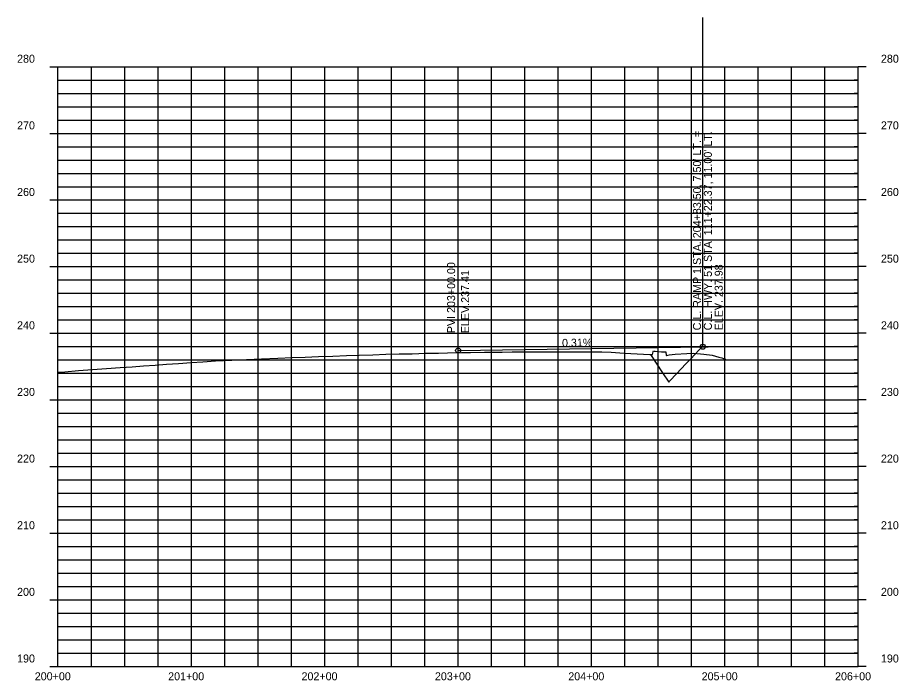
# Model space of a CAD drawing. Extents: x 921603 to 924670, y 1759276 to 1766491.
# Drawn here: x 921610 to 922270, y 1763922 to 1764419 of the extents above; entities that cross this region are included whole.
import ezdxf

# ---------------------------------------------------------------- set-up
doc = ezdxf.new("R2010")
doc.units = 0
for name, color, linetype in [('63', 7, 'Continuous'), ('R_Axis_Annotation', 7, 'Continuous'), ('R_Exist Surface', 7, 'Continuous'), ('R_Grid', 7, 'Continuous'), ('R_Grid Annot', 7, 'Continuous'), ('R_Grid_Minor', 7, 'Continuous'), ('R_Prop Surface', 7, 'Continuous'), ('R_Vert Alg', 7, 'Continuous'), ('R_Vert Alg Annot', 7, 'Continuous')]:
    doc.layers.add(name, color=color, linetype=linetype)

msp = doc.modelspace()

# ---------------------------------------------------------------- linework, layer by layer
at = {"layer": 'R_Exist Surface'}
msp.add_lwpolyline([(921639.83, 1764153.1), (921644.89, 1764153.44), (921655.24, 1764154.22), (921665.73, 1764155.01), (921676.14, 1764155.79), (921686.57, 1764156.57), (921695.41, 1764157.21), (921703.94, 1764157.79), (921712.75, 1764158.42), (921721.3, 1764159), (921730.18, 1764159.68), (921739.57, 1764160.24), (921748.44, 1764160.92), (921757.85, 1764161.49), (921770.14, 1764162.03), (921781.25, 1764162.57), (921792.41, 1764163.11), (921804.66, 1764163.65), (921815.33, 1764164.06), (921825.24, 1764164.4), (921835.2, 1764164.74), (921845.82, 1764165.15), (921856.12, 1764165.51), (921865.74, 1764165.82), (921875.99, 1764166.17), (921885.66, 1764166.48), (921895.52, 1764166.77), (921905.37, 1764166.96), (921915.3, 1764167.25), (921925.09, 1764167.43), (921931.78, 1764167.48), (921942.35, 1764167.75), (921949.03, 1764167.79), (921959.64, 1764168.07), (921966.31, 1764168.11), (921972.96, 1764168.15), (921980.28, 1764168.28), (921992.27, 1764168.27), (921999.25, 1764168.38), (921999.45, 1764168.39), (922004.63, 1764168.38), (922020.25, 1764168.36), (922027.49, 1764168.32), (922028.2, 1764168.36), (922029.24, 1764168.44), (922036.73, 1764168.34), (922041.05, 1764168.32), (922047.65, 1764168.23), (922054.47, 1764167.97), (922064.29, 1764167.35), (922069.42, 1764167.21), (922083.53, 1764166.28), (922084.11, 1764166.26), (922085.62, 1764166.29), (922086.09, 1764168.32), (922086.29, 1764168.99), (922086.8, 1764168.83), (922087.46, 1764168.76), (922089.9, 1764168.61), (922092.39, 1764168.39), (922093.96, 1764168.4), (922095.17, 1764168.29), (922095.19, 1764168.28), (922095.59, 1764168.26), (922095.64, 1764168.25), (922095.65, 1764168.23), (922095.88, 1764165.5), (922095.94, 1764165.48), (922097.07, 1764165.93), (922098.01, 1764166.06), (922102.53, 1764166.7), (922111.27, 1764167.11), (922116.36, 1764167.36), (922124.05, 1764166.49), (922130.33, 1764165.73), (922135.25, 1764164.39), (922137.44, 1764163.82), (922138.89, 1764163.33), (922139.87, 1764163.04), (922140.24, 1764162.82)], dxfattribs=at)
at = {"layer": 'R_Grid'}
for p, q in [((921639.83, 1763932.26), (921639.83, 1764382.26)), ((921639.83, 1764382.26), (922239.83, 1764382.26)), ((921639.83, 1764382.26), (922239.83, 1764382.26)), ((921739.83, 1763932.26), (921739.83, 1764382.26)), ((921839.83, 1763932.26), (921839.83, 1764382.26)), ((921939.83, 1763932.26), (921939.83, 1764382.26)), ((922039.83, 1763932.26), (922039.83, 1764382.26)), ((922139.83, 1763932.26), (922139.83, 1764382.26)), ((922239.83, 1763932.26), (922239.83, 1764382.26)), ((921639.83, 1764332.26), (922239.83, 1764332.26)), ((921639.83, 1764282.26), (922239.83, 1764282.26)), ((921639.83, 1764232.26), (922239.83, 1764232.26)), ((921639.83, 1764182.26), (922239.83, 1764182.26)), ((921639.83, 1764132.26), (922239.83, 1764132.26)), ((921639.83, 1764082.26), (922239.83, 1764082.26)), ((921639.83, 1764032.26), (922239.83, 1764032.26)), ((921639.83, 1763982.26), (922239.83, 1763982.26)), ((921639.83, 1763932.26), (922239.83, 1763932.26))]:
    msp.add_line(p, q, dxfattribs=at)
at = {"layer": 'R_Grid Annot'}
for p, q in [((921633.83, 1764382.26), (921639.83, 1764382.26)), ((921633.83, 1764382.26), (921639.83, 1764382.26)), ((922245.83, 1764382.26), (922239.83, 1764382.26)), ((922245.83, 1764382.26), (922239.83, 1764382.26)), ((921639.83, 1764372.26), (921642.83, 1764372.26)), ((922239.83, 1764372.26), (922236.83, 1764372.26)), ((921639.83, 1764362.26), (921642.83, 1764362.26)), ((922239.83, 1764362.26), (922236.83, 1764362.26)), ((921639.83, 1764352.26), (921642.83, 1764352.26)), ((922239.83, 1764352.26), (922236.83, 1764352.26)), ((921639.83, 1764342.26), (921642.83, 1764342.26)), ((922239.83, 1764342.26), (922236.83, 1764342.26)), ((921633.83, 1764332.26), (921639.83, 1764332.26)), ((922245.83, 1764332.26), (922239.83, 1764332.26)), ((921639.83, 1764322.26), (921642.83, 1764322.26)), ((922239.83, 1764322.26), (922236.83, 1764322.26)), ((921639.83, 1764312.26), (921642.83, 1764312.26)), ((922239.83, 1764312.26), (922236.83, 1764312.26)), ((921639.83, 1764302.26), (921642.83, 1764302.26)), ((922239.83, 1764302.26), (922236.83, 1764302.26)), ((921639.83, 1764292.26), (921642.83, 1764292.26)), ((922239.83, 1764292.26), (922236.83, 1764292.26)), ((921633.83, 1764282.26), (921639.83, 1764282.26)), ((922245.83, 1764282.26), (922239.83, 1764282.26)), ((921639.83, 1764272.26), (921642.83, 1764272.26)), ((922239.83, 1764272.26), (922236.83, 1764272.26)), ((921639.83, 1764262.26), (921642.83, 1764262.26)), ((922239.83, 1764262.26), (922236.83, 1764262.26)), ((921639.83, 1764252.26), (921642.83, 1764252.26)), ((922239.83, 1764252.26), (922236.83, 1764252.26)), ((921639.83, 1764242.26), (921642.83, 1764242.26)), ((922239.83, 1764242.26), (922236.83, 1764242.26)), ((921633.83, 1764232.26), (921639.83, 1764232.26)), ((922245.83, 1764232.26), (922239.83, 1764232.26)), ((921639.83, 1764222.26), (921642.83, 1764222.26)), ((922239.83, 1764222.26), (922236.83, 1764222.26)), ((921639.83, 1764212.26), (921642.83, 1764212.26)), ((922239.83, 1764212.26), (922236.83, 1764212.26)), ((921639.83, 1764202.26), (921642.83, 1764202.26)), ((922239.83, 1764202.26), (922236.83, 1764202.26)), ((921639.83, 1764192.26), (921642.83, 1764192.26)), ((922239.83, 1764192.26), (922236.83, 1764192.26)), ((921633.83, 1764182.26), (921639.83, 1764182.26)), ((922245.83, 1764182.26), (922239.83, 1764182.26)), ((921639.83, 1764172.26), (921642.83, 1764172.26)), ((922239.83, 1764172.26), (922236.83, 1764172.26)), ((921639.83, 1764162.26), (921642.83, 1764162.26)), ((922239.83, 1764162.26), (922236.83, 1764162.26)), ((921639.83, 1764152.26), (921642.83, 1764152.26)), ((922239.83, 1764152.26), (922236.83, 1764152.26)), ((921639.83, 1764142.26), (921642.83, 1764142.26)), ((922239.83, 1764142.26), (922236.83, 1764142.26)), ((921633.83, 1764132.26), (921639.83, 1764132.26)), ((922245.83, 1764132.26), (922239.83, 1764132.26)), ((921639.83, 1764122.26), (921642.83, 1764122.26)), ((922239.83, 1764122.26), (922236.83, 1764122.26)), ((921639.83, 1764112.26), (921642.83, 1764112.26)), ((922239.83, 1764112.26), (922236.83, 1764112.26)), ((921639.83, 1764102.26), (921642.83, 1764102.26)), ((922239.83, 1764102.26), (922236.83, 1764102.26)), ((921639.83, 1764092.26), (921642.83, 1764092.26)), ((922239.83, 1764092.26), (922236.83, 1764092.26)), ((921633.83, 1764082.26), (921639.83, 1764082.26)), ((922245.83, 1764082.26), (922239.83, 1764082.26)), ((921639.83, 1764072.26), (921642.83, 1764072.26)), ((922239.83, 1764072.26), (922236.83, 1764072.26)), ((921639.83, 1764062.26), (921642.83, 1764062.26)), ((922239.83, 1764062.26), (922236.83, 1764062.26)), ((921639.83, 1764052.26), (921642.83, 1764052.26)), ((922239.83, 1764052.26), (922236.83, 1764052.26)), ((921639.83, 1764042.26), (921642.83, 1764042.26)), ((922239.83, 1764042.26), (922236.83, 1764042.26)), ((921633.83, 1764032.26), (921639.83, 1764032.26)), ((922245.83, 1764032.26), (922239.83, 1764032.26)), ((921639.83, 1764022.26), (921642.83, 1764022.26)), ((922239.83, 1764022.26), (922236.83, 1764022.26)), ((921639.83, 1764012.26), (921642.83, 1764012.26)), ((922239.83, 1764012.26), (922236.83, 1764012.26)), ((921639.83, 1764002.26), (921642.83, 1764002.26)), ((922239.83, 1764002.26), (922236.83, 1764002.26)), ((921639.83, 1763992.26), (921642.83, 1763992.26)), ((922239.83, 1763992.26), (922236.83, 1763992.26)), ((921633.83, 1763982.26), (921639.83, 1763982.26)), ((922245.83, 1763982.26), (922239.83, 1763982.26)), ((921639.83, 1763972.26), (921642.83, 1763972.26)), ((922239.83, 1763972.26), (922236.83, 1763972.26)), ((921639.83, 1763962.26), (921642.83, 1763962.26)), ((922239.83, 1763962.26), (922236.83, 1763962.26)), ((921639.83, 1763952.26), (921642.83, 1763952.26)), ((922239.83, 1763952.26), (922236.83, 1763952.26)), ((921639.83, 1763942.26), (921642.83, 1763942.26)), ((922239.83, 1763942.26), (922236.83, 1763942.26)), ((921633.83, 1763932.26), (921639.83, 1763932.26)), ((922245.83, 1763932.26), (922239.83, 1763932.26))]:
    msp.add_line(p, q, dxfattribs=at)
at = {"layer": 'R_Grid_Minor'}
for p, q in [((921664.83, 1763932.26), (921664.83, 1764382.26)), ((921689.83, 1763932.26), (921689.83, 1764382.26)), ((921714.83, 1763932.26), (921714.83, 1764382.26)), ((921764.83, 1763932.26), (921764.83, 1764382.26)), ((921789.83, 1763932.26), (921789.83, 1764382.26)), ((921814.83, 1763932.26), (921814.83, 1764382.26)), ((921864.83, 1763932.26), (921864.83, 1764382.26)), ((921889.83, 1763932.26), (921889.83, 1764382.26)), ((921914.83, 1763932.26), (921914.83, 1764382.26)), ((921964.83, 1763932.26), (921964.83, 1764382.26)), ((921989.83, 1763932.26), (921989.83, 1764382.26)), ((922014.83, 1763932.26), (922014.83, 1764382.26)), ((922064.83, 1763932.26), (922064.83, 1764382.26)), ((922089.83, 1763932.26), (922089.83, 1764382.26)), ((922114.83, 1763932.26), (922114.83, 1764382.26)), ((922164.83, 1763932.26), (922164.83, 1764382.26)), ((922189.83, 1763932.26), (922189.83, 1764382.26)), ((922214.83, 1763932.26), (922214.83, 1764382.26)), ((921639.83, 1764372.26), (922239.83, 1764372.26)), ((921639.83, 1764362.26), (922239.83, 1764362.26)), ((921639.83, 1764352.26), (922239.83, 1764352.26)), ((921639.83, 1764342.26), (922239.83, 1764342.26)), ((921639.83, 1764322.26), (922239.83, 1764322.26)), ((921639.83, 1764312.26), (922239.83, 1764312.26)), ((921639.83, 1764302.26), (922239.83, 1764302.26)), ((921639.83, 1764292.26), (922239.83, 1764292.26)), ((921639.83, 1764272.26), (922239.83, 1764272.26)), ((921639.83, 1764262.26), (922239.83, 1764262.26)), ((921639.83, 1764252.26), (922239.83, 1764252.26)), ((921639.83, 1764242.26), (922239.83, 1764242.26)), ((921639.83, 1764222.26), (922239.83, 1764222.26)), ((921639.83, 1764212.26), (922239.83, 1764212.26)), ((921639.83, 1764202.26), (922239.83, 1764202.26)), ((921639.83, 1764192.26), (922239.83, 1764192.26)), ((921639.83, 1764172.26), (922239.83, 1764172.26)), ((921639.83, 1764162.26), (922239.83, 1764162.26)), ((921639.83, 1764152.26), (922239.83, 1764152.26)), ((921639.83, 1764142.26), (922239.83, 1764142.26)), ((921639.83, 1764122.26), (922239.83, 1764122.26)), ((921639.83, 1764112.26), (922239.83, 1764112.26)), ((921639.83, 1764102.26), (922239.83, 1764102.26)), ((921639.83, 1764092.26), (922239.83, 1764092.26)), ((921639.83, 1764072.26), (922239.83, 1764072.26)), ((921639.83, 1764062.26), (922239.83, 1764062.26)), ((921639.83, 1764052.26), (922239.83, 1764052.26)), ((921639.83, 1764042.26), (922239.83, 1764042.26)), ((921639.83, 1764022.26), (922239.83, 1764022.26)), ((921639.83, 1764012.26), (922239.83, 1764012.26)), ((921639.83, 1764002.26), (922239.83, 1764002.26)), ((921639.83, 1763992.26), (922239.83, 1763992.26)), ((921639.83, 1763972.26), (922239.83, 1763972.26)), ((921639.83, 1763962.26), (922239.83, 1763962.26)), ((921639.83, 1763952.26), (922239.83, 1763952.26)), ((921639.83, 1763942.26), (922239.83, 1763942.26))]:
    msp.add_line(p, q, dxfattribs=at)
at = {"layer": 'R_Prop Surface'}
msp.add_lwpolyline([(922084.18, 1764166.26), (922093.07, 1764152.71), (922097.73, 1764145.62), (922098.34, 1764146.26), (922098.57, 1764146.51), (922103.65, 1764151.9), (922110.67, 1764159.36), (922114.23, 1764163.14), (922117.22, 1764166.32), (922120.44, 1764169.74), (922122.69, 1764172.14), (922123.33, 1764172.16), (922124.81, 1764172.17), (922127.23, 1764172.2), (922135.39, 1764172.24), (922137.37, 1764172.26), (922139.71, 1764172.21)], dxfattribs=at)
at = {"layer": 'R_Vert Alg'}
msp.add_line((921939.83, 1764169.32), (922123.33, 1764172.16), dxfattribs=at)
at = {"layer": 'R_Vert Alg Annot'}
for p, q in [((922123.33, 1764182.16), (922123.33, 1764419.11)), ((921939.83, 1764179.32), (921939.83, 1764263.32)), ((921939.83, 1764169.32), (921939.83, 1764179.32)), ((922123.33, 1764172.16), (922123.33, 1764182.16))]:
    msp.add_line(p, q, dxfattribs=at)
for centre in [(922123.33, 1764172.16), (921939.83, 1764169.32)]:
    msp.add_circle(centre, 1.85, dxfattribs=at)

# ---------------------------------------------------------------- texts
at = {"layer": '63'}
msp.add_text('-', height=0.0001, dxfattribs=at).set_placement((921639.83, 1763932.26))
at = {"layer": 'R_Axis_Annotation'}
for s, p in [('280', (921609.16, 1764385.26)), ('280', (921609.16, 1764385.26)), ('280', (922256.84, 1764385.26)), ('280', (922256.84, 1764385.26)), ('270', (921609.16, 1764335.26)), ('270', (922256.84, 1764335.26)), ('260', (921609.16, 1764285.26)), ('260', (922256.84, 1764285.26)), ('250', (921609.16, 1764235.26)), ('250', (922256.84, 1764235.26)), ('240', (921609.16, 1764185.26)), ('240', (922256.84, 1764185.26)), ('230', (921609.16, 1764135.26)), ('230', (922256.84, 1764135.26)), ('220', (921609.16, 1764085.26)), ('220', (922256.84, 1764085.26)), ('210', (921609.16, 1764035.26)), ('210', (922256.84, 1764035.26)), ('200', (921609.16, 1763985.26)), ('200', (922256.84, 1763985.26)), ('190', (921609.16, 1763935.26)), ('190', (922256.84, 1763935.26)), ('200+00', (921622.42, 1763921.91)), ('201+00', (921722.42, 1763921.91)), ('202+00', (921822.42, 1763921.91)), ('203+00', (921922.42, 1763921.91)), ('204+00', (922022.42, 1763921.91)), ('205+00', (922122.42, 1763921.91)), ('206+00', (922222.42, 1763921.91))]:
    msp.add_text(s, height=6, dxfattribs=at).set_placement(p)
at = {"layer": 'R_Vert Alg Annot'}
for s, rotation, p in [("C.L. RAMP 1 STA. 204+83.50, 7.50' LT. =", 90, (922121.95, 1764184.47)), ("C.L. HWY. 51 STA. 111+22.37, 11.00' LT.", 90, (922130.08, 1764184.47)), ('PVI 203+00.00', 90, (921937.58, 1764182.32)), ('ELEV. 237.98', 90, (922138.21, 1764184.47)), ('ELEV.237.41', 90, (921948.08, 1764182.32)), ('0.31%', 0.88801, (922017.76, 1764172.02))]:
    msp.add_text(s, height=6, rotation=rotation, dxfattribs=at).set_placement(p)

doc.saveas('drawing.dxf')
